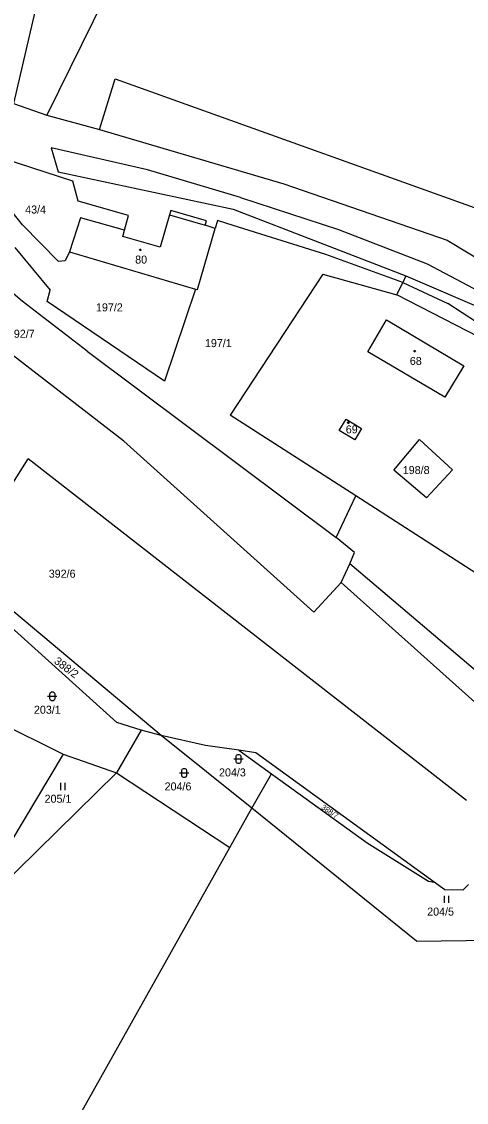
# Model space of a CAD drawing. Extents: x -811039 to -805820, y -1161436 to -1155864.
# Drawn here: x -806387 to -806292.6, y -1158211 to -1157981.5 of the extents above; entities that cross this region are included whole.
import ezdxf

# ---------------------------------------------------------------- set-up
doc = ezdxf.new("R2010")
doc.units = 0
for name, color, linetype in [('Default', 7, 'Continuous'), ('KN_HRANICE', 7, 'Continuous'), ('KN_KULTURY', 7, 'Continuous'), ('KN_PARCELY', 7, 'Continuous'), ('KN_SLUCKY', 7, 'Continuous')]:
    doc.layers.add(name, color=color, linetype=linetype)

# ---------------------------------------------------------------- blocks, each defined once
blk = doc.blocks.new('306')
at = {"layer": 'Default'}
for p, q in [((-0.5, 1.5), (-0.5, 0)), ((0.5, 0), (0.5, 1.5))]:
    blk.add_line(p, q, dxfattribs=at)
blk = doc.blocks.new('316')
at = {"layer": 'Default'}
for points in [[(-1, 1), (0.27, 1), (1, 1)], [(-0.5, 1.5), (-0.4, 1.79), (-0.15, 1.97), (0.16, 1.97), (0.41, 1.79), (0.51, 1.5), (0.51, 0.5), (0.41, 0.21), (0.16, 0.03), (-0.15, 0.03), (-0.4, 0.21), (-0.5, 0.5), (-0.5, 1.5)]]:
    blk.add_lwpolyline(points, dxfattribs=at)
blk = doc.blocks.new('402')
at = {"layer": 'Default'}
blk.add_lwpolyline([(0.09, 0.15), (0.18, 0), (0.09, -0.15), (-0.09, -0.15), (-0.18, 0), (-0.09, 0.15), (0.09, 0.15)], dxfattribs=at)

msp = doc.modelspace()

# ---------------------------------------------------------------- linework, layer by layer
at = {"layer": 'KN_HRANICE'}
for p, q in [((-806356.95, -1157951.21), (-806381.62, -1158001.34)), ((-806383.1, -1157974.77), (-806388.68, -1157998.88)), ((-806370.44, -1158004.38), (-806367.13, -1157993.6)), ((-806367.13, -1157993.6), (-806289.91, -1158021.33)), ((-806388.68, -1157998.88), (-806381.62, -1158001.34)), ((-806381.62, -1158001.34), (-806370.44, -1158004.38)), ((-806370.44, -1158004.38), (-806331.33, -1158015.9)), ((-806380.73, -1158008.27), (-806379.23, -1158013.41)), ((-806360.28, -1158012.96), (-806380.73, -1158008.27)), ((-806376.12, -1158015.37), (-806390.69, -1158010.65)), ((-806340.53, -1158018.83), (-806360.28, -1158012.96)), ((-806379.23, -1158013.41), (-806342.05, -1158021.28)), ((-806374.96, -1158019.64), (-806376.12, -1158015.37)), ((-806386.8, -1158024.62), (-806393.59, -1158016.18)), ((-806331.33, -1158015.9), (-806296.62, -1158027.91)), ((-806364.3, -1158022.68), (-806374.96, -1158019.64)), ((-806340.53, -1158018.83), (-806319.73, -1158025.59)), ((-806355.27, -1158021.6), (-806355.56, -1158022.54)), ((-806347.71, -1158023.77), (-806355.27, -1158021.6)), ((-806342.05, -1158021.28), (-806305.43, -1158035.44)), ((-806379.13, -1158032.44), (-806386.8, -1158024.62)), ((-806374.49, -1158023.11), (-806376.79, -1158030.39)), ((-806365.13, -1158025.77), (-806374.49, -1158023.11)), ((-806365.13, -1158025.77), (-806364.3, -1158022.68)), ((-806355.56, -1158022.54), (-806357.59, -1158029.4)), ((-806347.99, -1158024.73), (-806347.71, -1158023.77)), ((-806345.88, -1158025.39), (-806347.99, -1158024.73)), ((-806345.39, -1158023.71), (-806345.88, -1158025.39)), ((-806342.09, -1158024.75), (-806345.39, -1158023.71)), ((-806322.43, -1158030.93), (-806342.09, -1158024.75)), ((-806386.86, -1158040.87), (-806403.97, -1158026.28)), ((-806365.51, -1158027.09), (-806365.13, -1158025.77)), ((-806357.59, -1158029.4), (-806365.51, -1158027.09)), ((-806349.67, -1158038.37), (-806345.88, -1158025.39)), ((-806319.73, -1158025.59), (-806300.91, -1158032.94)), ((-806296.62, -1158027.91), (-806275.48, -1158040.73)), ((-806388.41, -1158029.46), (-806380.92, -1158038.53)), ((-806376.79, -1158030.39), (-806377.73, -1158032.27)), ((-806376.79, -1158030.39), (-806350.05, -1158038.26)), ((-806306.08, -1158036.87), (-806322.43, -1158030.93)), ((-806377.73, -1158032.27), (-806379.13, -1158032.44)), ((-806300.91, -1158032.94), (-806278.74, -1158044.68)), ((-806323.03, -1158035.12), (-806342.67, -1158065.06)), ((-806323.03, -1158035.12), (-806307.33, -1158039.47)), ((-806305.43, -1158035.44), (-806306.08, -1158036.87)), ((-806305.43, -1158035.44), (-806287.42, -1158043.15)), ((-806365.29, -1158070.57), (-806407.54, -1158037.9)), ((-806381.53, -1158040.9), (-806380.92, -1158038.53)), ((-806350.05, -1158038.26), (-806356.63, -1158057.8)), ((-806350.05, -1158038.26), (-806349.67, -1158038.37)), ((-806307.33, -1158039.47), (-806306.08, -1158036.87)), ((-806306.08, -1158036.87), (-806296.48, -1158041.34)), ((-806286.23, -1158050.39), (-806307.33, -1158039.47)), ((-806373.03, -1158051.43), (-806386.86, -1158040.87)), ((-806356.63, -1158057.8), (-806381.53, -1158040.9)), ((-806237, -1158080.46), (-806296.48, -1158041.34)), ((-806313.5, -1158051.6), (-806309.54, -1158044.84)), ((-806309.54, -1158044.84), (-806293.1, -1158054.57)), ((-806373.03, -1158051.43), (-806320.21, -1158091.05)), ((-806297.13, -1158061.26), (-806313.5, -1158051.6)), ((-806293.1, -1158054.57), (-806297.13, -1158061.26)), ((-806316.03, -1158082.21), (-806342.67, -1158065.06)), ((-806319.53, -1158068.32), (-806318.06, -1158065.9)), ((-806318.06, -1158065.9), (-806314.8, -1158067.87)), ((-806316.26, -1158070.31), (-806319.53, -1158068.32)), ((-806314.8, -1158067.87), (-806316.26, -1158070.31)), ((-806324.96, -1158106.89), (-806365.29, -1158070.57)), ((-806307.96, -1158076.73), (-806302.54, -1158070.22)), ((-806302.54, -1158070.22), (-806295.49, -1158076.69)), ((-806391.65, -1158083.89), (-806385.61, -1158074.34)), ((-806292.53, -1158146.89), (-806385.61, -1158074.34)), ((-806301.02, -1158082.62), (-806307.96, -1158076.73)), ((-806295.49, -1158076.69), (-806301.02, -1158082.62)), ((-806320.21, -1158091.05), (-806316.03, -1158082.21)), ((-806233.89, -1158135.1), (-806316.03, -1158082.21)), ((-806316.32, -1158094.25), (-806320.21, -1158091.05)), ((-806317.28, -1158096.64), (-806316.32, -1158094.25)), ((-806319.13, -1158100.62), (-806317.28, -1158096.64)), ((-806253.69, -1158150.72), (-806317.28, -1158096.64)), ((-806319.13, -1158100.62), (-806324.96, -1158106.89)), ((-806319.13, -1158100.62), (-806268.96, -1158145.58)), ((-806357.33, -1158133.11), (-806388.61, -1158106.79)), ((-806366.79, -1158130.31), (-806390, -1158109.34)), ((-806399.36, -1158126.56), (-806378.19, -1158137.05)), ((-806361.6, -1158131.96), (-806366.79, -1158130.31)), ((-806361.6, -1158131.96), (-806366.81, -1158140.98)), ((-806357.33, -1158133.11), (-806361.6, -1158131.96)), ((-806338.08, -1158148.49), (-806357.33, -1158133.11)), ((-806347.97, -1158135.23), (-806357.33, -1158133.11)), ((-806378.19, -1158137.05), (-806394.81, -1158164.93)), ((-806378.19, -1158137.05), (-806366.81, -1158140.98)), ((-806340.83, -1158136.23), (-806347.97, -1158135.23)), ((-806337.24, -1158136.73), (-806340.83, -1158136.23)), ((-806340.83, -1158136.23), (-806333.9, -1158141.2)), ((-806299.41, -1158164.2), (-806337.24, -1158136.73)), ((-806366.81, -1158140.98), (-806393.9, -1158167.57)), ((-806366.81, -1158140.98), (-806342.79, -1158156.88)), ((-806338.08, -1158148.49), (-806333.9, -1158141.2)), ((-806333.9, -1158141.2), (-806313.63, -1158155.9)), ((-806342.79, -1158156.88), (-806338.08, -1158148.49)), ((-806303.18, -1158176.76), (-806338.08, -1158148.49)), ((-806391.51, -1158243.66), (-806342.79, -1158156.88)), ((-806313.63, -1158155.9), (-806300.63, -1158164.02)), ((-806300.63, -1158164.02), (-806299.41, -1158164.2)), ((-806297.16, -1158165.83), (-806299.41, -1158164.2)), ((-806293.29, -1158165.96), (-806292.09, -1158164.72)), ((-806293.29, -1158165.96), (-806297.16, -1158165.83)), ((-806303.18, -1158176.76), (-806271.6, -1158176.32))]:
    msp.add_line(p, q, dxfattribs=at)
at = {"layer": 'KN_SLUCKY'}
msp.add_line((-806355.56, -1158022.54), (-806347.99, -1158024.73), dxfattribs=at)

# ---------------------------------------------------------------- block references
at = {"layer": 'KN_KULTURY'}
for name, p in [('402', (-806361.8, -1158029.94)), ('402', (-806303.53, -1158051.46)), ('402', (-806317.65, -1158066.65)), ('316', (-806380.47, -1158125.76)), ('316', (-806340.94, -1158139.07)), ('316', (-806352.49, -1158142.04)), ('306', (-806378.21, -1158144.66)), ('306', (-806296.75, -1158168.63))]:
    msp.add_blockref(name, p, dxfattribs=at)

# ---------------------------------------------------------------- texts
at = {"layer": 'KN_PARCELY'}
for s, p in [('43/4', (-806386.22, -1158022.23)), ('80', (-806362.87, -1158032.86)), ('197/2', (-806371.19, -1158043.01)), ('392/7', (-806389.89, -1158048.61)), ('197/1', (-806348.06, -1158050.6)), ('68', (-806304.56, -1158054.39)), ('69', (-806318.16, -1158068.92)), ('198/8', (-806306.06, -1158077.56)), ('392/6', (-806381.22, -1158099.57)), ('203/1', (-806384.36, -1158128.46)), ('204/3', (-806345.07, -1158141.77)), ('204/6', (-806356.62, -1158144.74)), ('205/1', (-806382.1, -1158147.36)), ('204/5', (-806300.88, -1158171.33))]:
    msp.add_text(s, height=1.7, dxfattribs=at).set_placement(p)
for s, height, rotation, p in [('388/2', 1.7, 323.148, (-806380.24, -1158117.61)), ('388/7', 1.14, 326.242, (-806323.48, -1158148.59))]:
    msp.add_text(s, height=height, rotation=rotation, dxfattribs=at).set_placement(p)

doc.saveas('drawing.dxf')
